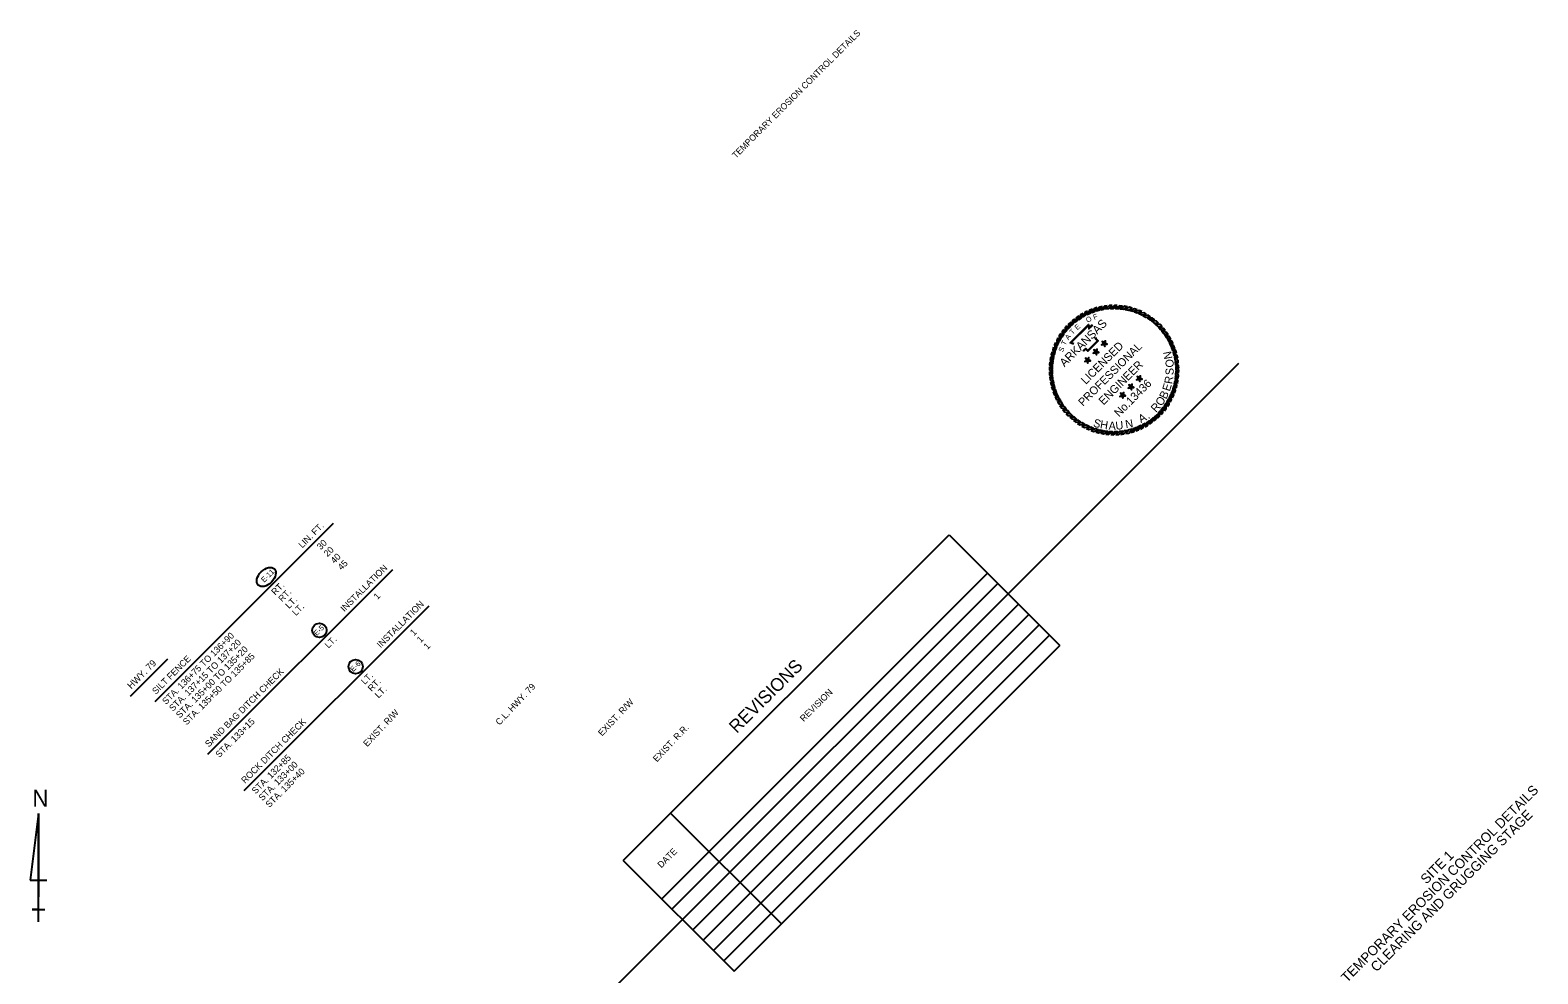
# Model space of a CAD drawing. Extents: x 1377476 to 1378879, y 1932630 to 1934097.
# Drawn here: x 1377489 to 1378879, y 1933226 to 1934097 of the extents above; entities that cross this region are included whole.
import ezdxf

# ---------------------------------------------------------------- set-up
doc = ezdxf.new("R2010")
doc.units = 0
for name, color, linetype in [('1', 7, 'Continuous'), ('44', 7, 'Continuous'), ('60', 7, 'Continuous'), ('63', 7, 'Continuous'), ('Default', 7, 'Continuous'), ('G-ANNO-SYMB', 7, 'Continuous'), ('R_Draft', 7, 'Continuous')]:
    doc.layers.add(name, color=color, linetype=linetype)

msp = doc.modelspace()

# ---------------------------------------------------------------- linework, layer by layer
at = {"layer": '1'}
for p, q in [((1378390.8, 1933576.6), (1378603.6, 1933789.5)), ((1377887.9, 1933073.8), (1378090.3, 1933276.1))]:
    msp.add_line(p, q, dxfattribs=at)
for centre in [(1377755.5, 1933543), (1377788.9, 1933509.5)]:
    msp.add_circle(centre, 6.61, dxfattribs=at)
msp.add_ellipse((1377706.5, 1933592.2), major_axis=(7.44, 7.44), ratio=0.638788, dxfattribs=at)
at = {"layer": '44'}
for p, q in [((1377604, 1933477.4), (1377768.6, 1933642)), ((1377652.7, 1933428.6), (1377823.2, 1933599)), ((1377686.2, 1933395.2), (1377856.6, 1933565.6)), ((1377581.2, 1933482.3), (1377615.7, 1933516.8))]:
    msp.add_line(p, q, dxfattribs=at)
at = {"layer": '63'}
for p, q in [((1377496.3, 1933374), (1377488.7, 1933312.5)), ((1377496.3, 1933274), (1377496.3, 1933374)), ((1377496.3, 1933374), (1377496.3, 1933297.1)), ((1377488.7, 1933312.5), (1377504, 1933312.5)), ((1377496.3, 1933274), (1377496.3, 1933297.1)), ((1377496.3, 1933285.5), (1377490.6, 1933285.5)), ((1377490.6, 1933285.5), (1377502.1, 1933285.5)), ((1377496.3, 1933274), (1377496.3, 1933285.5))]:
    msp.add_line(p, q, dxfattribs=at)
at = {"layer": 'Default'}
for p, q in [((1378035.8, 1933330.6), (1378336.3, 1933631.1)), ((1378336.3, 1933631.1), (1378438.5, 1933528.9)), ((1378071.2, 1933295.2), (1378371.7, 1933595.7)), ((1378080.7, 1933285.7), (1378381.2, 1933586.2)), ((1378090.3, 1933276.1), (1378390.8, 1933576.6)), ((1378099.8, 1933266.6), (1378400.3, 1933567.1)), ((1378099.8, 1933266.6), (1378400.3, 1933567.1)), ((1378109.4, 1933257), (1378409.9, 1933557.5)), ((1378118.9, 1933247.5), (1378419.4, 1933548)), ((1378128.5, 1933237.9), (1378429, 1933538.5)), ((1378138, 1933228.4), (1378438.5, 1933528.9)), ((1378079.5, 1933374.3), (1378181.7, 1933272.1)), ((1378035.8, 1933330.6), (1378138, 1933228.4))]:
    msp.add_line(p, q, dxfattribs=at)
at = {"layer": 'G-ANNO-SYMB'}
for points in [[(1378468.5, 1933839.4), (1378466.1, 1933838.4), (1378463.8, 1933834.5), (1378466.4, 1933835.6)], [(1378472.9, 1933840.8), (1378470.5, 1933840), (1378467.9, 1933836.2), (1378470.5, 1933837.2)], [(1378477.5, 1933841.8), (1378475, 1933841.3), (1378472.2, 1933837.7), (1378474.8, 1933838.4)], [(1378482.1, 1933842.5), (1378479.6, 1933842.1), (1378476.5, 1933838.8), (1378479.2, 1933839.3)], [(1378486.8, 1933842.8), (1378484.3, 1933842.7), (1378480.9, 1933839.6), (1378483.6, 1933839.9)], [(1378491.5, 1933842.7), (1378488.9, 1933842.8), (1378485.3, 1933840), (1378488.1, 1933840.1)], [(1378496.2, 1933842.3), (1378493.6, 1933842.6), (1378489.8, 1933840.1), (1378492.6, 1933839.9)], [(1378500.8, 1933841.5), (1378498.3, 1933842), (1378494.3, 1933839.8), (1378497, 1933839.5)], [(1378505.3, 1933840.4), (1378502.9, 1933841.1), (1378498.7, 1933839.2), (1378501.4, 1933838.6)], [(1378509.8, 1933838.9), (1378507.4, 1933839.8), (1378503.1, 1933838.2), (1378505.7, 1933837.4)], [(1378514.1, 1933837.1), (1378511.7, 1933838.1), (1378507.3, 1933836.9), (1378509.9, 1933835.9)], [(1378445.1, 1933824.1), (1378443.4, 1933822.2), (1378443.2, 1933817.7), (1378445, 1933819.8)], [(1378448.5, 1933827.4), (1378446.6, 1933825.6), (1378446.1, 1933821.1), (1378448, 1933823.1)], [(1378452.1, 1933830.4), (1378450.1, 1933828.8), (1378449.2, 1933824.3), (1378451.2, 1933826.2)], [(1378455.9, 1933833.1), (1378453.8, 1933831.7), (1378452.5, 1933827.3), (1378454.7, 1933829)], [(1378459.9, 1933835.5), (1378457.7, 1933834.2), (1378456.1, 1933830), (1378458.4, 1933831.5)], [(1378464.1, 1933837.6), (1378461.8, 1933836.5), (1378459.9, 1933832.4), (1378462.3, 1933833.7)], [(1378518.2, 1933834.9), (1378516, 1933836.1), (1378511.5, 1933835.3), (1378514, 1933834.1)], [(1378522.2, 1933832.4), (1378520, 1933833.8), (1378515.5, 1933833.3), (1378517.9, 1933831.9)], [(1378526, 1933829.6), (1378523.9, 1933831.2), (1378519.4, 1933831), (1378521.6, 1933829.5)], [(1378529.5, 1933826.5), (1378527.6, 1933828.3), (1378523, 1933828.5), (1378525.2, 1933826.7)], [(1378532.8, 1933823.2), (1378531, 1933825.1), (1378526.5, 1933825.6), (1378528.5, 1933823.7)], [(1378436.8, 1933812.9), (1378435.6, 1933810.6), (1378436.4, 1933806.1), (1378437.6, 1933808.6)], [(1378439.3, 1933816.8), (1378437.9, 1933814.7), (1378438.4, 1933810.1), (1378439.8, 1933812.6)], [(1378442.1, 1933820.6), (1378440.5, 1933818.6), (1378440.7, 1933814), (1378442.2, 1933816.3)], [(1378535.8, 1933819.6), (1378534.2, 1933821.6), (1378529.7, 1933822.5), (1378531.5, 1933820.5)], [(1378538.5, 1933815.8), (1378537, 1933817.9), (1378532.6, 1933819.2), (1378534.3, 1933817)], [(1378540.9, 1933811.8), (1378539.6, 1933814), (1378535.3, 1933815.6), (1378536.8, 1933813.3)], [(1378543, 1933807.6), (1378541.9, 1933809.9), (1378537.7, 1933811.8), (1378539.1, 1933809.4)], [(1378431.3, 1933800), (1378430.6, 1933797.5), (1378432.5, 1933793.3), (1378433.1, 1933796)], [(1378432.8, 1933804.4), (1378431.9, 1933802), (1378433.5, 1933797.7), (1378434.3, 1933800.4)], [(1378434.6, 1933808.7), (1378433.6, 1933806.4), (1378434.8, 1933802), (1378435.8, 1933804.6)], [(1378471.7, 1933800), (1378470.7, 1933800.1), (1378469.3, 1933798.7), (1378471.3, 1933799)], [(1378471.7, 1933800), (1378471.6, 1933801), (1378469.8, 1933801.9), (1378470.7, 1933800.1)], [(1378471.7, 1933800), (1378471.3, 1933799), (1378472.2, 1933797.3), (1378472.5, 1933799.2)], [(1378471.7, 1933800), (1378472.7, 1933800.4), (1378473, 1933802.4), (1378471.6, 1933801)], [(1378471.7, 1933800), (1378472.5, 1933799.2), (1378474.4, 1933799.5), (1378472.7, 1933800.4)], [(1378479.4, 1933807.7), (1378478.4, 1933807.8), (1378477, 1933806.4), (1378479, 1933806.7)], [(1378479.4, 1933807.7), (1378479.3, 1933808.7), (1378477.5, 1933809.6), (1378478.4, 1933807.8)], [(1378479.4, 1933807.7), (1378479, 1933806.7), (1378479.9, 1933805), (1378480.2, 1933806.9)], [(1378479.4, 1933807.7), (1378480.4, 1933808.1), (1378480.7, 1933810.1), (1378479.3, 1933808.7)], [(1378479.4, 1933807.7), (1378480.2, 1933806.9), (1378482.1, 1933807.2), (1378480.4, 1933808.1)], [(1378544.7, 1933803.2), (1378543.8, 1933805.6), (1378539.8, 1933807.9), (1378541, 1933805.3)], [(1378546.1, 1933798.7), (1378545.4, 1933801.2), (1378541.6, 1933803.8), (1378542.5, 1933801.2)], [(1378547.2, 1933794.2), (1378546.6, 1933796.7), (1378543.1, 1933799.5), (1378543.8, 1933796.9)], [(1378428.9, 1933786.1), (1378428.9, 1933783.6), (1378431.7, 1933780), (1378431.6, 1933782.7)], [(1378429.4, 1933790.8), (1378429.1, 1933788.3), (1378431.6, 1933784.4), (1378431.7, 1933787.2)], [(1378430.1, 1933795.4), (1378429.7, 1933792.9), (1378431.9, 1933788.9), (1378432.2, 1933791.7)], [(1378464, 1933792.2), (1378463, 1933792.4), (1378461.6, 1933791), (1378463.5, 1933791.3)], [(1378464, 1933792.2), (1378463.8, 1933793.3), (1378462.1, 1933794.2), (1378463, 1933792.4)], [(1378464, 1933792.2), (1378463.5, 1933791.3), (1378464.4, 1933789.6), (1378464.7, 1933791.5)], [(1378464, 1933792.2), (1378464.9, 1933792.7), (1378465.2, 1933794.7), (1378463.8, 1933793.3)], [(1378464, 1933792.2), (1378464.7, 1933791.5), (1378466.7, 1933791.8), (1378464.9, 1933792.7)], [(1378547.8, 1933789.5), (1378547.5, 1933792.1), (1378544.2, 1933795.2), (1378544.7, 1933792.5)], [(1378548.2, 1933784.9), (1378548, 1933787.4), (1378544.9, 1933790.8), (1378545.2, 1933788)], [(1378548.1, 1933780.2), (1378548.2, 1933782.7), (1378545.4, 1933786.3), (1378545.5, 1933783.6)], [(1378428.9, 1933781.5), (1378429, 1933778.9), (1378432.1, 1933775.5), (1378431.8, 1933778.3)], [(1378429.2, 1933776.8), (1378429.5, 1933774.2), (1378432.9, 1933771.1), (1378432.4, 1933773.8)], [(1378429.9, 1933772.1), (1378430.4, 1933769.6), (1378434, 1933766.8), (1378433.3, 1933769.5)], [(1378504, 1933767.7), (1378503.9, 1933768.7), (1378502.1, 1933769.6), (1378503, 1933767.8)], [(1378504, 1933767.7), (1378505, 1933768.1), (1378505.3, 1933770.1), (1378503.9, 1933768.7)], [(1378511.7, 1933775.4), (1378510.7, 1933775.5), (1378509.3, 1933774.1), (1378511.3, 1933774.4)], [(1378511.7, 1933775.4), (1378511.6, 1933776.4), (1378509.8, 1933777.3), (1378510.7, 1933775.5)], [(1378511.7, 1933775.4), (1378511.3, 1933774.4), (1378512.2, 1933772.7), (1378512.5, 1933774.6)], [(1378511.7, 1933775.4), (1378512.7, 1933775.8), (1378513, 1933777.8), (1378511.6, 1933776.4)], [(1378511.7, 1933775.4), (1378512.5, 1933774.6), (1378514.4, 1933774.9), (1378512.7, 1933775.8)], [(1378544.3, 1933761.9), (1378545.1, 1933764.3), (1378543.6, 1933768.6), (1378542.8, 1933766)], [(1378545.8, 1933766.4), (1378546.4, 1933768.8), (1378544.5, 1933773), (1378544, 1933770.3)], [(1378546.9, 1933770.9), (1378547.4, 1933773.4), (1378545.2, 1933777.4), (1378544.8, 1933774.7)], [(1378547.7, 1933775.5), (1378548, 1933778.1), (1378545.4, 1933781.9), (1378545.3, 1933779.1)], [(1378430.9, 1933767.6), (1378431.7, 1933765.1), (1378435.4, 1933762.6), (1378434.5, 1933765.2)], [(1378432.3, 1933763.1), (1378433.2, 1933760.7), (1378437.2, 1933758.5), (1378436.1, 1933761)], [(1378434.1, 1933758.8), (1378435.2, 1933756.4), (1378439.3, 1933754.5), (1378438, 1933756.9)], [(1378436.2, 1933754.6), (1378437.4, 1933752.3), (1378441.7, 1933750.7), (1378440.2, 1933753.1)], [(1378496.3, 1933759.9), (1378495.3, 1933760.1), (1378493.9, 1933758.7), (1378495.8, 1933759)], [(1378496.3, 1933759.9), (1378496.2, 1933761), (1378494.4, 1933761.9), (1378495.3, 1933760.1)], [(1378496.3, 1933759.9), (1378495.8, 1933759), (1378496.7, 1933757.2), (1378497.1, 1933759.2)], [(1378496.3, 1933759.9), (1378497.2, 1933760.4), (1378497.6, 1933762.4), (1378496.2, 1933761)], [(1378496.3, 1933759.9), (1378497.1, 1933759.2), (1378499, 1933759.5), (1378497.2, 1933760.4)], [(1378504, 1933767.7), (1378503, 1933767.8), (1378501.6, 1933766.4), (1378503.6, 1933766.7)], [(1378504, 1933767.7), (1378503.6, 1933766.7), (1378504.5, 1933765), (1378504.8, 1933766.9)], [(1378504, 1933767.7), (1378504.8, 1933766.9), (1378506.7, 1933767.2), (1378505, 1933768.1)], [(1378537.8, 1933749.5), (1378539.2, 1933751.6), (1378538.7, 1933756.2), (1378537.3, 1933753.8)], [(1378540.3, 1933753.5), (1378541.5, 1933755.7), (1378540.6, 1933760.2), (1378539.4, 1933757.7)], [(1378542.4, 1933757.6), (1378543.5, 1933759.9), (1378542.3, 1933764.4), (1378541.3, 1933761.8)], [(1378438.6, 1933750.5), (1378440, 1933748.4), (1378444.4, 1933747.2), (1378442.7, 1933749.4)], [(1378441.3, 1933746.7), (1378442.9, 1933744.7), (1378447.4, 1933743.8), (1378445.5, 1933745.9)], [(1378444.3, 1933743.1), (1378446, 1933741.3), (1378450.6, 1933740.7), (1378448.6, 1933742.6)], [(1378525, 1933735.9), (1378527, 1933737.5), (1378527.9, 1933742), (1378525.8, 1933740.1)], [(1378528.6, 1933738.9), (1378530.4, 1933740.7), (1378531, 1933745.2), (1378529.1, 1933743.2)], [(1378531.9, 1933742.2), (1378533.6, 1933744.1), (1378533.8, 1933748.7), (1378532.1, 1933746.5)], [(1378535, 1933745.7), (1378536.5, 1933747.8), (1378536.4, 1933752.3), (1378534.8, 1933750)], [(1378447.6, 1933739.8), (1378449.5, 1933738.1), (1378454, 1933737.9), (1378451.9, 1933739.6)], [(1378451.1, 1933736.7), (1378453.1, 1933735.1), (1378457.7, 1933735.3), (1378455.4, 1933736.9)], [(1378454.9, 1933733.9), (1378457, 1933732.5), (1378461.5, 1933733), (1378459.1, 1933734.4)], [(1378458.8, 1933731.4), (1378461.1, 1933730.2), (1378465.6, 1933731.1), (1378463.1, 1933732.2)], [(1378463, 1933729.3), (1378465.3, 1933728.2), (1378469.7, 1933729.4), (1378467.1, 1933730.4)], [(1378467.3, 1933727.4), (1378469.7, 1933726.6), (1378474, 1933728.1), (1378471.3, 1933728.9)], [(1378471.7, 1933725.9), (1378474.2, 1933725.2), (1378478.4, 1933727.1), (1378475.6, 1933727.7)], [(1378476.3, 1933724.8), (1378478.8, 1933724.3), (1378482.8, 1933726.5), (1378480, 1933726.9)], [(1378490.2, 1933723.5), (1378492.8, 1933723.7), (1378496.2, 1933726.7), (1378493.4, 1933726.4)], [(1378494.9, 1933723.8), (1378497.4, 1933724.2), (1378500.6, 1933727.5), (1378497.8, 1933727)], [(1378499.5, 1933724.5), (1378502, 1933725.1), (1378504.9, 1933728.6), (1378502.2, 1933727.9)], [(1378504.1, 1933725.6), (1378506.6, 1933726.3), (1378509.1, 1933730.1), (1378506.5, 1933729.1)], [(1378508.6, 1933727), (1378511, 1933727.9), (1378513.2, 1933731.9), (1378510.7, 1933730.7)], [(1378512.9, 1933728.7), (1378515.2, 1933729.8), (1378517.2, 1933734), (1378514.7, 1933732.6)], [(1378517.1, 1933730.8), (1378519.3, 1933732.1), (1378520.9, 1933736.4), (1378518.6, 1933734.8)], [(1378521.1, 1933733.2), (1378523.3, 1933734.7), (1378524.5, 1933739), (1378522.3, 1933737.3)], [(1378480.9, 1933724), (1378483.4, 1933723.7), (1378487.2, 1933726.2), (1378484.5, 1933726.4)], [(1378485.5, 1933723.6), (1378488.1, 1933723.5), (1378491.7, 1933726.3), (1378488.9, 1933726.2)]]:
    msp.add_lwpolyline(points, close=True, dxfattribs=at)
for points in [[(1378451.1, 1933807), (1378448, 1933808.2), (1378465, 1933825.2), (1378465.4, 1933822), (1378466.5, 1933823.2), (1378467.5, 1933824.1), (1378468.6, 1933825)], [(1378451.3, 1933807.4), (1378448.7, 1933808.3), (1378464.8, 1933824.4), (1378465.1, 1933821.1), (1378466.8, 1933822.9), (1378467.8, 1933823.9), (1378468.8, 1933824.7)], [(1378471.6, 1933813.2), (1378471.6, 1933812.7), (1378471.8, 1933812.3), (1378472.6, 1933811.3), (1378473.8, 1933810.1), (1378464.3, 1933800.6), (1378462.7, 1933802.2), (1378462.4, 1933802.6), (1378461.9, 1933802.3), (1378460.5, 1933800.9), (1378459.9, 1933801.1)], [(1378471.3, 1933813.3), (1378471.2, 1933812.6), (1378471.5, 1933812), (1378472.3, 1933811), (1378473.3, 1933810.1), (1378464.3, 1933801.2), (1378463, 1933802.5), (1378462.4, 1933803), (1378461.6, 1933802.6), (1378460.4, 1933801.3), (1378460, 1933801.4)]]:
    msp.add_lwpolyline(points, dxfattribs=at)

# ---------------------------------------------------------------- texts
at = {"layer": '1'}
for s, height, p in [('TEMPORARY EROSION CONTROL DETAILS', 5.862, (1378139.6, 1933978.1)), ('E-11', 4.8, (1377704.5, 1933586.8)), ('E-5 ', 4.8, (1377753, 1933537.6)), ('E-6 ', 4.8, (1377786.7, 1933504.4))]:
    msp.add_text(s, height=height, rotation=45, dxfattribs=at).set_placement(p)
at = {"layer": '44'}
for s, height, p in [('LIN. FT.', 6, (1377739.7, 1933618.4)), ('30', 6, (1377756.7, 1933616.8)), ('20', 6, (1377763, 1933610.4)), ('40', 6, (1377769.4, 1933604.1)), ('45', 6, (1377775.9, 1933598)), ('INSTALLATION', 6, (1377778.5, 1933559.7)), ('RT.', 6, (1377714.7, 1933575)), ('RT.', 6, (1377721.1, 1933568.7)), ('1', 6, (1377809.1, 1933570.9)), ('LT.', 6, (1377727.5, 1933562.5)), ('LT.', 6, (1377733.8, 1933556.1)), ('INSTALLATION', 6, (1377812, 1933526.3)), ('STA. 136+75 TO 136+90', 6, (1377614, 1933474.1)), ('STA. 137+15 TO 137+20', 6, (1377620.4, 1933467.8)), ('LT.', 6, (1377763.9, 1933526)), ('1', 6, (1377842.6, 1933537.5)), ('1', 6, (1377848.9, 1933531.1)), ('SILT FENCE      ', 6, (1377604.7, 1933483.4)), ('STA. 135+00 TO 135+20', 6, (1377626.7, 1933461.5)), ('STA. 135+50 TO 135+85', 6, (1377633, 1933455.1)), ('1', 6, (1377855.2, 1933524.8)), ('HWY. 79', 6.25, (1377581.9, 1933488.4)), ('SAND BAG DITCH CHECK', 6, (1377653.5, 1933434.7)), ('LT.', 6, (1377797.4, 1933492.5)), ('RT.', 6, (1377803.6, 1933486.1)), ('LT.', 6, (1377810.1, 1933479.9)), ('STA. 133+15', 6, (1377663.1, 1933425)), ('ROCK DITCH CHECK', 6, (1377686.9, 1933401.2)), ('STA. 132+85', 6, (1377696.6, 1933391.5)), ('STA. 133+00', 6, (1377702.9, 1933385.2)), ('STA. 135+40', 6, (1377709.3, 1933378.9))]:
    msp.add_text(s, height=height, rotation=45, dxfattribs=at).set_placement(p)
at = {"layer": '60'}
for s, p in [('TEMPORARY EROSION CONTROL DETAILS', (1378703.4, 1933217.4)), ('CLEARING AND GRUGGING STAGE', (1378730.6, 1933227.2)), ('SITE 1', (1378776.6, 1933308.2))]:
    msp.add_text(s, height=9, rotation=45, dxfattribs=at).set_placement(p)
at = {"layer": '63'}
msp.add_text('N', height=15.4, rotation=360, dxfattribs=at).set_placement((1377490.7, 1933380.4))
at = {"layer": 'Default'}
for s, height, p in [('REVISIONS', 12, (1378140.5, 1933447.2)), ('REVISION', 6, (1378202.3, 1933458.2)), ('DATE', 6, (1378070.9, 1933323.2))]:
    msp.add_text(s, height=height, rotation=45, dxfattribs=at).set_placement(p)
at = {"layer": 'G-ANNO-SYMB'}
for s, height, rotation, p in [('ARKANSAS', 7.75, 45, (1378442.8, 1933785.6)), ('E', 4.75, 41.672, (1378454.6, 1933819.8)), ('O', 4.75, 26.2218, (1378463.9, 1933826.8)), ('F', 4.75, 20.3628, (1378470.2, 1933829.5)), ('T', 4.75, 61.9015, (1378443.5, 1933805.5)), ('A', 4.75, 53.6788, (1378446.5, 1933810.6)), ('T', 4.75, 46.4789, (1378450.2, 1933815.6)), ('S', 4.75, 64.7726, (1378441.2, 1933799.3)), ('PROFESSIONAL', 7.5, 45, (1378459.9, 1933749.2)), ('LICENSED', 7.5, 45, (1378462.4, 1933769.4)), ('N', 7.5, 101.1007, (1378542.4, 1933794)), ('ENGINEER', 7.5, 45, (1378478.8, 1933750.4)), ('S', 7.5, 88.4878, (1378543.4, 1933778.4)), ('O', 7.5, 89.7757, (1378543.5, 1933785.5)), ('No.13436', 7.47, 45, (1378493.1, 1933739.5)), ('E', 7.5, 72.8315, (1378539.9, 1933763.1)), ('R', 7.5, 80.6597, (1378542.1, 1933769.9)), ('O', 7.5, 56.4296, (1378532.3, 1933749.3)), ('B', 7.5, 63.885, (1378536.5, 1933755.8)), ('A', 7.5, 28.0991, (1378513.3, 1933734.1)), ('R', 7.5, 48.2287, (1378527.2, 1933743.6)), ('S', 7.5, 343.1636, (1378468.7, 1933731.3)), ('H', 7.5, 350.619, (1378475.2, 1933729.6)), ('A', 7.5, 358.4472, (1378483.4, 1933728.1)), ('U', 7.5, 5.9026, (1378490.2, 1933728)), ('N', 7.5, 9.9326, (1378499.5, 1933729.4)), ('.', 7.5, 36.3, (1378520.1, 1933737.7))]:
    msp.add_text(s, height=height, rotation=rotation, dxfattribs=at).set_placement(p)
at = {"layer": 'R_Draft'}
for s, p in [('C.L. HWY. 79', (1377921.6, 1933454.9)), ('EXIST. R/W', (1378016.2, 1933444.9)), ('EXIST. R/W', (1377799.6, 1933435.1)), ('EXIST. R.R.', (1378066.8, 1933421))]:
    msp.add_text(s, height=6, rotation=46.6607, dxfattribs=at).set_placement(p)

doc.saveas('drawing.dxf')
